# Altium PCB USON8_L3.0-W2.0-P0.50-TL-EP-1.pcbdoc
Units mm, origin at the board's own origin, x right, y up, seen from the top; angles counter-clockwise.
Board outline 16.35 x 14.99 mm, 2 copper layers (Top Layer, Bottom Layer), stack 0 mm thick; 1 components, 0 nets, 9 pads, 0 vias.
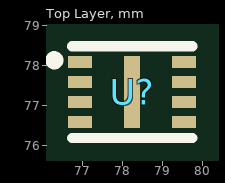
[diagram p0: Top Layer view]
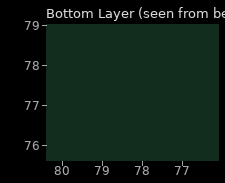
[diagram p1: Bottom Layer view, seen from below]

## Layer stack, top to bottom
Top Layer: signal copper (thickness not stored)
Bottom Layer: signal copper (thickness not stored)

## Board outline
86.2,69.85 69.85,69.85 69.85,84.841 86.2,84.841

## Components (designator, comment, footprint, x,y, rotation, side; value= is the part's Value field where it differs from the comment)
U? "" USON8_L3.0-W2.0-P0.50-TL-EP-1 78.25,77.351 r0 top

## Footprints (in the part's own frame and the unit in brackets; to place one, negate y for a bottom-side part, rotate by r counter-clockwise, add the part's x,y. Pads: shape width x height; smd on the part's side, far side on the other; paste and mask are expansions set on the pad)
USON8_L3.0-W2.0-P0.50-TL-EP-1 [mm]
  rect 0.6x0.3 smd: 1(-1.3,0.75) 2(-1.3,0.25) 3(-1.3,-0.25) 4(-1.3,-0.75) 5(1.3,-0.75) 6(1.3,-0.25) 7(1.3,0.25) 8(1.3,0.75)
  rect 0.4x1.8 smd: 9(0,0)
  silkscreen extent -2.05,-1.15 1.5,1.14

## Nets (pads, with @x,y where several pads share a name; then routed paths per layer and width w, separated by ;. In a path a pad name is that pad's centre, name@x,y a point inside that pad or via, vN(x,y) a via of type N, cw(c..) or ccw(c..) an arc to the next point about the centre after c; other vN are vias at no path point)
pads on no net: U?.1 U?.2 U?.3 U?.4 U?.5 U?.6 U?.7 U?.8 U?.9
